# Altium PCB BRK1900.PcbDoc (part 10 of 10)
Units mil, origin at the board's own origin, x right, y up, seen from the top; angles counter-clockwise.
Board outline 8858.27 x 5905.51 mil, 10 copper layers (L1-TOP, L2-GND, L3-SIG1, L4-GND, L5-PWR, L6-PWR, L7-GND, L8-SIG2, L9-GND, L10-BOT), stack 48.824 mil thick; 507 components, 607 nets, 2498 pads, 2210 vias.
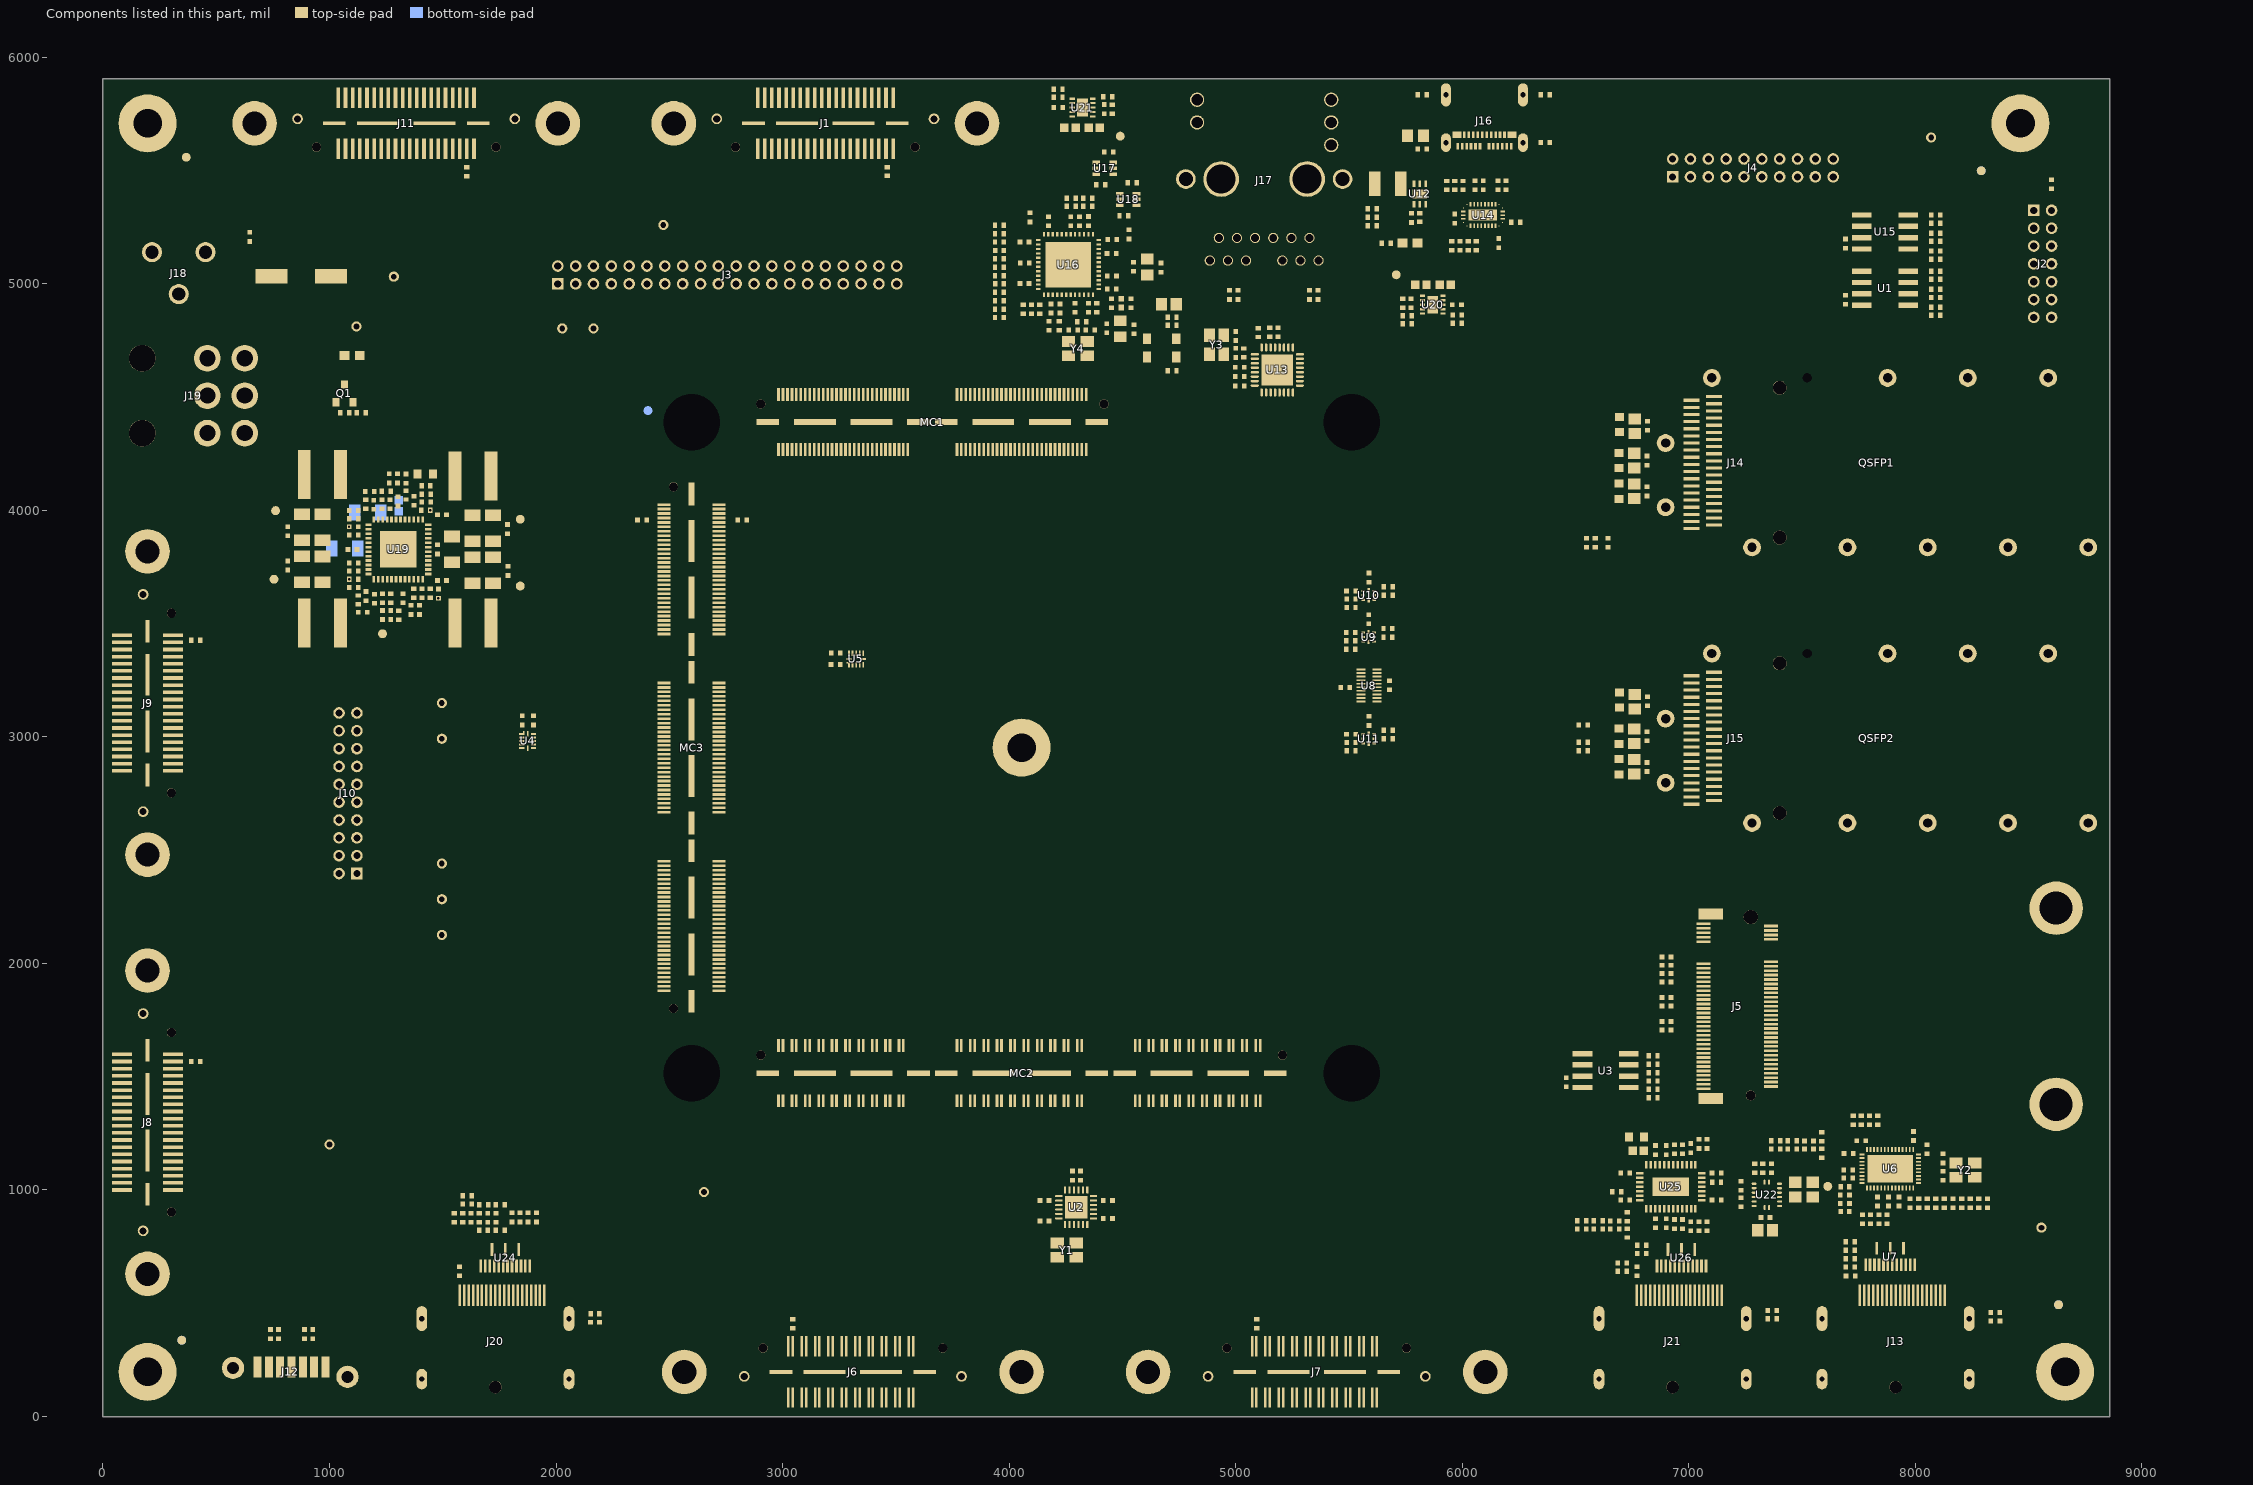
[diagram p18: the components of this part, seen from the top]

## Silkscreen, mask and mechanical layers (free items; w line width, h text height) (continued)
Drill Drawing:
  drawing of 183 lines, arcs and shapes, not listed
  text "DRILL TABLE" at 9113,5525.02 h50
  text "Symbol" at 9172.63,5408.47 h47.91
  text "Count" at 9519.93,5408.47 h47.91
  text "Finished Hole Size" at 9965.66,5408.47 h47.91
  text "Slot Length" at 10871.71,5408.47 h47.91
  text "Plated" at 11603.45,5408.47 h47.91
  text "Drill Layer Pair" at 11950.76,5408.47 h47.91
  text "Via/Pad" at 12753.04,5408.47 h47.91
  text "Hole Tolerance (+)" at 13156.22,5408.47 h47.91
  text "Hole Tolerance (-)" at 14054.29,5408.47 h47.91
  text "Comment" at 14952.35,5408.47 h47.91
  text "2214" at 9519.93,5308.66 h39.92
  text "10.00mil (0.254mm)" at 9965.66,5308.66 h39.92
  text "-" at 10871.71,5308.66 h39.92
  text "PTH" at 11603.45,5308.66 h39.92
  text "L1-TOP - L10-BOT" at 11950.76,5308.66 h39.92
  text "(Mixed)" at 12753.04,5308.66 h39.92
  text "3.00mil (0.076mm)" at 13156.22,5308.66 h39.92
  text "3.00mil (0.076mm)" at 14054.29,5308.66 h39.92
  text "2" at 9519.93,5208.86 h39.92
  text "23.62mil (0.600mm)" at 9965.66,5208.86 h39.92
  text "62.99mil (1.600mm)" at 10871.71,5208.86 h39.92
  text "PTH" at 11603.45,5208.86 h39.92
  text "L1-TOP - L10-BOT" at 11950.76,5208.86 h39.92
  text "Pad" at 12753.04,5208.86 h39.92
  text "3.00mil (0.076mm)" at 13156.22,5208.86 h39.92
  text "3.00mil (0.076mm)" at 14054.29,5208.86 h39.92
  text "6" at 9519.93,5109.05 h39.92
  text "23.62mil (0.600mm)" at 9965.66,5109.05 h39.92
  text "66.93mil (1.700mm)" at 10871.71,5109.05 h39.92
  text "PTH" at 11603.45,5109.05 h39.92
  text "L1-TOP - L10-BOT" at 11950.76,5109.05 h39.92
  text "Pad" at 12753.04,5109.05 h39.92
  text "3.00mil (0.076mm)" at 13156.22,5109.05 h39.92
  text "3.00mil (0.076mm)" at 14054.29,5109.05 h39.92
  text "E" at 9150.97,5099.06 h44.36
  text "2" at 9519.93,5009.24 h39.92
  text "23.62mil (0.600mm)" at 9965.66,5009.24 h39.92
  text "82.68mil (2.100mm)" at 10871.71,5009.24 h39.92
  text "PTH" at 11603.45,5009.24 h39.92
  text "L1-TOP - L10-BOT" at 11950.76,5009.24 h39.92
  text "Pad" at 12753.04,5009.24 h39.92
  text "3.00mil (0.076mm)" at 13156.22,5009.24 h39.92
  text "3.00mil (0.076mm)" at 14054.29,5009.24 h39.92
  text "6" at 9519.93,4909.43 h39.92
  text "23.62mil (0.600mm)" at 9965.66,4909.43 h39.92
  text "86.61mil (2.200mm)" at 10871.71,4909.43 h39.92
  text "PTH" at 11603.45,4909.43 h39.92
  text "L1-TOP - L10-BOT" at 11950.76,4909.43 h39.92
  text "Pad" at 12753.04,4909.43 h39.92
  text "3.00mil (0.076mm)" at 13156.22,4909.43 h39.92
  text "3.00mil (0.076mm)" at 14054.29,4909.43 h39.92
  text "14" at 9519.93,4809.63 h39.92
  text "25.00mil (0.635mm)" at 9965.66,4809.63 h39.92
  text "-" at 10871.71,4809.63 h39.92
  text "PTH" at 11603.45,4809.63 h39.92
  text "L1-TOP - L10-BOT" at 11950.76,4809.63 h39.92
  text "Pad" at 12753.04,4809.63 h39.92
  text "3.00mil (0.076mm)" at 13156.22,4809.63 h39.92
  text "3.00mil (0.076mm)" at 14054.29,4809.63 h39.92
  text "12" at 9519.93,4709.82 h39.92
  text "31.50mil (0.800mm)" at 9965.66,4709.82 h39.92
  text "-" at 10871.71,4709.82 h39.92
  text "PTH" at 11603.45,4709.82 h39.92
  text "L1-TOP - L10-BOT" at 11950.76,4709.82 h39.92
  text "Pad" at 12753.04,4709.82 h39.92
  text "3.00mil (0.076mm)" at 13156.22,4709.82 h39.92
  text "3.00mil (0.076mm)" at 14054.29,4709.82 h39.92
  text "94" at 9519.93,4610.01 h39.92
  text "31.50mil (0.800mm)" at 9965.66,4610.01 h39.92
  text "-" at 10871.71,4610.01 h39.92
  text "PTH" at 11603.45,4610.01 h39.92
  text "L1-TOP - L10-BOT" at 11950.76,4610.01 h39.92
  text "Pad" at 12753.04,4610.01 h39.92
  text "3.15mil (0.080mm)" at 13156.22,4610.01 h39.92
  text "3.15mil (0.080mm)" at 14054.29,4610.01 h39.92
  text "C" at 9150.97,4600.02 h44.36
  text "12" at 9519.93,4510.21 h39.92
  text "35.04mil (0.890mm)" at 9965.66,4510.21 h39.92
  text "-" at 10871.71,4510.21 h39.92
  text "PTH" at 11603.45,4510.21 h39.92
  text "L1-TOP - L10-BOT" at 11950.76,4510.21 h39.92
  text "Pad" at 12753.04,4510.21 h39.92
  text "5.00mil (0.127mm)" at 13156.22,4510.21 h39.92
  text "0.00mil (0.000mm)" at 14054.29,4510.21 h39.92
  text "A" at 9150.97,4500.21 h44.36
  text "18" at 9519.93,4410.4 h39.92
  text "40.16mil (1.020mm)" at 9965.66,4410.4 h39.92
  text "-" at 10871.71,4410.4 h39.92
  text "NPTH" at 11603.45,4410.4 h39.92
  text "L1-TOP - L10-BOT" at 11950.76,4410.4 h39.92
  text "Pad" at 12753.04,4410.4 h39.92
  text "3.00mil (0.076mm)" at 13156.22,4410.4 h39.92
  text "3.00mil (0.076mm)" at 14054.29,4410.4 h39.92
  text "2" at 9519.93,4310.59 h39.92
  text "41.34mil (1.050mm)" at 9965.66,4310.59 h39.92
  text "-" at 10871.71,4310.59 h39.92
  text "NPTH" at 11603.45,4310.59 h39.92
  text "L1-TOP - L10-BOT" at 11950.76,4310.59 h39.92
  text "Pad" at 12753.04,4310.59 h39.92
  text "3.00mil (0.076mm)" at 13156.22,4310.59 h39.92
  text "3.00mil (0.076mm)" at 14054.29,4310.59 h39.92
  text "J" at 9150.97,4300.6 h44.36
  text "22" at 9519.93,4210.78 h39.92
  text "41.34mil (1.050mm)" at 9965.66,4210.78 h39.92
  text "-" at 10871.71,4210.78 h39.92
  text "PTH" at 11603.45,4210.78 h39.92
  text "L1-TOP - L10-BOT" at 11950.76,4210.78 h39.92
  text "Pad" at 12753.04,4210.78 h39.92
  text "3.00mil (0.076mm)" at 13156.22,4210.78 h39.92
  text "3.00mil (0.076mm)" at 14054.29,4210.78 h39.92
  text "M" at 9150.97,4200.79 h44.36
  text "1" at 9519.93,4110.98 h39.92
  text "43.31mil (1.100mm)" at 9965.66,4110.98 h39.92
  text "-" at 10871.71,4110.98 h39.92
  text "NPTH" at 11603.45,4110.98 h39.92
  text "L1-TOP - L10-BOT" at 11950.76,4110.98 h39.92
  text "Pad" at 12753.04,4110.98 h39.92
  text "3.00mil (0.076mm)" at 13156.22,4110.98 h39.92
  text "3.00mil (0.076mm)" at 14054.29,4110.98 h39.92
  text "5" at 9519.93,4011.17 h39.92
  text "50.00mil (1.270mm)" at 9965.66,4011.17 h39.92
  text "-" at 10871.71,4011.17 h39.92
  text "PTH" at 11603.45,4011.17 h39.92
  text "L1-TOP - L10-BOT" at 11950.76,4011.17 h39.92
  text "Pad" at 12753.04,4011.17 h39.92
  text "4.00mil (0.102mm)" at 13156.22,4011.17 h39.92
  text "4.00mil (0.102mm)" at 14054.29,4011.17 h39.92
  text "N" at 9150.97,4001.18 h44.36
  text "2" at 9519.93,3911.36 h39.92
  text "53.15mil (1.350mm)" at 9965.66,3911.36 h39.92
  text "-" at 10871.71,3911.36 h39.92
  text "PTH" at 11603.45,3911.36 h39.92
  text "L1-TOP - L10-BOT" at 11950.76,3911.36 h39.92
  text "Pad" at 12753.04,3911.36 h39.92
  text "3.00mil (0.076mm)" at 13156.22,3911.36 h39.92
  text "3.00mil (0.076mm)" at 14054.29,3911.36 h39.92
  text "B" at 9150.97,3901.37 h44.36
  text "3" at 9519.93,3811.56 h39.92
  text "55.12mil (1.400mm)" at 9965.66,3811.56 h39.92
  text "-" at 10871.71,3811.56 h39.92
  text "NPTH" at 11603.45,3811.56 h39.92
  text "L1-TOP - L10-BOT" at 11950.76,3811.56 h39.92
  text "Pad" at 12753.04,3811.56 h39.92
  text "3.00mil (0.076mm)" at 13156.22,3811.56 h39.92
  text "3.00mil (0.076mm)" at 14054.29,3811.56 h39.92
  text "H" at 9150.97,3801.56 h44.36
  text "3" at 9519.93,3711.75 h39.92
  text "59.06mil (1.500mm)" at 9965.66,3711.75 h39.92
  text "-" at 10871.71,3711.75 h39.92
  text "PTH" at 11603.45,3711.75 h39.92
  text "L1-TOP - L10-BOT" at 11950.76,3711.75 h39.92
  text "Pad" at 12753.04,3711.75 h39.92
  text "3.00mil (0.076mm)" at 13156.22,3711.75 h39.92
  text "3.00mil (0.076mm)" at 14054.29,3711.75 h39.92
  text "4" at 9519.93,3611.94 h39.92
  text "61.02mil (1.550mm)" at 9965.66,3611.94 h39.92
  text "-" at 10871.71,3611.94 h39.92
  text "NPTH" at 11603.45,3611.94 h39.92
  text "L1-TOP - L10-BOT" at 11950.76,3611.94 h39.92
  text "Pad" at 12753.04,3611.94 h39.92
  text "3.00mil (0.076mm)" at 13156.22,3611.94 h39.92
  text "3.00mil (0.076mm)" at 14054.29,3611.94 h39.92
  text "D" at 9150.97,3601.95 h44.36
  text "2" at 9519.93,3512.13 h39.92
  text "62.00mil (1.575mm)" at 9965.66,3512.13 h39.92
  text "-" at 10871.71,3512.13 h39.92
  text "PTH" at 11603.45,3512.13 h39.92
  text "L1-TOP - L10-BOT" at 11950.76,3512.13 h39.92
  text "Pad" at 12753.04,3512.13 h39.92
  text "4.00mil (0.102mm)" at 13156.22,3512.13 h39.92
  text "4.00mil (0.102mm)" at 14054.29,3512.13 h39.92
  text "1" at 9519.93,3412.33 h39.92
  text "62.99mil (1.600mm)" at 9965.66,3412.33 h39.92
  text "-" at 10871.71,3412.33 h39.92
  text "NPTH" at 11603.45,3412.33 h39.92
  text "L1-TOP - L10-BOT" at 11950.76,3412.33 h39.92
  text "Pad" at 12753.04,3412.33 h39.92
  text "3.00mil (0.076mm)" at 13156.22,3412.33 h39.92
  text "3.00mil (0.076mm)" at 14054.29,3412.33 h39.92
  text "6" at 9519.93,3312.52 h39.92
  text "70.87mil (1.800mm)" at 9965.66,3312.52 h39.92
  text "-" at 10871.71,3312.52 h39.92
  text "PTH" at 11603.45,3312.52 h39.92
  text "L1-TOP - L10-BOT" at 11950.76,3312.52 h39.92
  text "Pad" at 12753.04,3312.52 h39.92
  text "3.00mil (0.076mm)" at 13156.22,3312.52 h39.92
  text "3.00mil (0.076mm)" at 14054.29,3312.52 h39.92
  text "12" at 9519.93,3212.71 h39.92
  text "106.30mil (2.700mm)" at 9965.66,3212.71 h39.92
  text "-" at 10871.71,3212.71 h39.92
  text "PTH" at 11603.45,3212.71 h39.92
  text "L1-TOP - L10-BOT" at 11950.76,3212.71 h39.92
  text "Pad" at 12753.04,3212.71 h39.92
  text "3.00mil (0.076mm)" at 13156.22,3212.71 h39.92
  text "3.00mil (0.076mm)" at 14054.29,3212.71 h39.92
  text "G" at 9150.97,3202.72 h44.36
  text "2" at 9519.93,3112.91 h39.92
  text "118.11mil (3.000mm)" at 9965.66,3112.91 h39.92
  text "-" at 10871.71,3112.91 h39.92
  text "NPTH" at 11603.45,3112.91 h39.92
  text "L1-TOP - L10-BOT" at 11950.76,3112.91 h39.92
  text "Pad" at 12753.04,3112.91 h39.92
  text "3.00mil (0.076mm)" at 13156.22,3112.91 h39.92
  text "3.00mil (0.076mm)" at 14054.29,3112.91 h39.92
  text "F" at 9150.97,3102.91 h44.36
  text "5" at 9519.93,3013.1 h39.92
  text "125.98mil (3.200mm)" at 9965.66,3013.1 h39.92
  text "-" at 10871.71,3013.1 h39.92
  text "PTH" at 11603.45,3013.1 h39.92
  text "L1-TOP - L10-BOT" at 11950.76,3013.1 h39.92
  text "Pad" at 12753.04,3013.1 h39.92
  text "3.00mil (0.076mm)" at 13156.22,3013.1 h39.92
  text "3.00mil (0.076mm)" at 14054.29,3013.1 h39.92
  text "O" at 9150.97,3003.11 h44.36
  text "2" at 9519.93,2913.29 h39.92
  text "128.00mil (3.251mm)" at 9965.66,2913.29 h39.92
  text "-" at 10871.71,2913.29 h39.92
  text "PTH" at 11603.45,2913.29 h39.92
  text "L1-TOP - L10-BOT" at 11950.76,2913.29 h39.92
  text "Pad" at 12753.04,2913.29 h39.92
  text "4.00mil (0.102mm)" at 13156.22,2913.29 h39.92
  text "4.00mil (0.102mm)" at 14054.29,2913.29 h39.92
  text "2" at 9519.93,2813.48 h39.92
  text "145.67mil (3.700mm)" at 9965.66,2813.48 h39.92
  text "-" at 10871.71,2813.48 h39.92
  text "PTH" at 11603.45,2813.48 h39.92
  text "L1-TOP - L10-BOT" at 11950.76,2813.48 h39.92
  text "Pad" at 12753.04,2813.48 h39.92
  text "3.00mil (0.076mm)" at 13156.22,2813.48 h39.92
  text "3.00mil (0.076mm)" at 14054.29,2813.48 h39.92
  text "4" at 9519.93,2713.68 h39.92
  text "250.00mil (6.350mm)" at 9965.66,2713.68 h39.92
  text "-" at 10871.71,2713.68 h39.92
  text "NPTH" at 11603.45,2713.68 h39.92
  text "L1-TOP - L10-BOT" at 11950.76,2713.68 h39.92
  text "Pad" at 12753.04,2713.68 h39.92
  text "3.00mil (0.076mm)" at 13156.22,2713.68 h39.92
  text "3.00mil (0.076mm)" at 14054.29,2713.68 h39.92
  text "I" at 9158.36,2703.68 h44.36
  text "2458 Total" at 9519.93,2613.87 h39.92
  text "Slot definitions :" at 9172.63,2510.72 h39.92
  text "Routed Path Length" at 9869.13,2510.72 h39.92
  text "= Calculated from tool start centre position to tool end centre position." at 10612.19,2510.72 h39.92
  text "Slot Length" at 9869.13,2437.5 h39.92
  text "= Routed Path Length + Tool Size = Slot length as defined in the PCB layout" at 10332.82,2437.5 h39.92
Doc-Assy-Top:
  lines w4.9: 6455.41,-1165.11 6455.41,-465.69 9394.83,-465.69 ; 6455.41,-929.08 9394.83,-929.08 ; 6899,-1165.11 6899,-929.08 ; 7587.2,-1165.11 7587.2,-929.08 ; 7724.8,-928.79 7724.8,-465.69 ; 8604.56,-1165.11 8604.56,-929.08
  lines w4.91: -809.63,527.32 -613.38,527.32 ; -809.63,2612.53 -613.38,2612.53 ; -809.63,4697.75 -613.38,4697.75 ; 1692.62,-1361.63 1692.62,-1165.38 ; 1692.62,6390.45 1692.62,6586.7 ; 4391.13,-1361.63 4391.13,-1165.38 ; 4391.13,6390.45 4391.13,6586.7 ; 5176.15,-1361.63 9591.89,-1361.63 ; 7089.64,-1361.63 7089.64,-1165.38 ; 7089.64,6390.45 7089.64,6586.7 ; 9395.64,527.32 9591.89,527.32 ; 9395.64,2612.53 9591.89,2612.53 ; 9395.64,4697.75 9591.89,4697.75 ; 9591.89,-1361.63 9591.89,6586.7 -809.63,6586.7 -809.63,-1361.63 9591.89,-1361.63 ; -613.38,-1165.38 -613.38,6390.45 9395.64,6390.45 9395.64,-1165.38 -613.38,-1165.38
  text "1" at 320.15,6457.32 h68.69
  text "2" at 3019.31,6457.32 h68.69
  text "3" at 5712.91,6457.32 h68.69
  text "4" at 8412.41,6457.32 h68.69
  text "NOTES: /  / 1. Hand place bottom-side components C113, C116, C140" at -411,5900.75 h50
  text "A" at -739.13,5651.55 h68.69
  text "A" at 9472.33,5651.55 h68.69
  text "B" at -739.13,3566.34 h68.69
  text "B" at 9472.33,3566.34 h68.69
  text "C" at -739.13,1481.12 h68.69
  text "C" at 9472.33,1481.12 h68.69
  text "TITLE:" at 6531.58,-542.92 h44.14
  text "Opal Kelly" at 7802.04,-573.82 h68.66
  text "D" at -739.13,-599.18 h68.69
  text "D" at 9472.33,-599.18 h68.69
  text "13500 SW 72nd Ave Suite 100" at 7802.04,-689.66 h68.66
  text "Portland, OR 97223" at 7802.04,-786.2 h68.66
  text "'.Part_Number' / Assembly Drawing" at 6563.33,-787.86 h68.66
  text "www.opalkelly.com" at 7802.04,-882.74 h68.66
  text "(Top)" at 6563.33,-899.67 h68.66
  text "REV:" at 6510.01,-994.48 h44.14
  text "SIZE:" at 6958.84,-994.48 h44.14
  text "ENGINEER:" at 7647.05,-994.48 h44.14
  text "DATE:" at 8664.4,-994.48 h44.14
  text "'.PCB_Revision'XX" at 6569.85,-1114.17 h68.66
  text "ANSI A" at 7018.68,-1114.17 h68.66
  text "NDK" at 7706.89,-1114.17 h68.66
  text ".PRINT_DATE" at 8724.24,-1114.17 h68.66
  text "1" at 320.15,-1300.94 h68.69
  text "2" at 3019.31,-1300.94 h68.69
  text "3" at 5712.91,-1300.94 h68.69
  text "4" at 8412.41,-1300.94 h68.69
Doc-Assy-Bot:
  lines w4.9: -611.4,-929.36 2327.29,-929.36 ; -611.4,-466.09 2327.29,-466.09 2327.29,-1165.33 ; 178.68,-1165.33 178.68,-929.36 ; 1058.21,-929.06 1058.21,-466.09 ; 1195.78,-1165.33 1195.78,-929.36 ; 1883.82,-1165.33 1883.82,-929.36
  lines w4.91: -808.42,526.69 -612.21,526.69 ; -808.42,2611.39 -612.21,2611.39 ; -808.42,4696.08 -612.21,4696.08 ; 1693.22,-1361.8 1693.22,-1165.6 ; 1693.22,6388.37 1693.22,6584.58 ; 3606.24,-1361.8 -808.42,-1361.8 ; 4391.07,-1361.8 4391.07,-1165.6 ; 4391.07,6388.37 4391.07,6584.58 ; 7088.91,-1361.8 7088.91,-1165.6 ; 7088.91,6388.37 7088.91,6584.58 ; 9394.34,526.69 9590.55,526.69 ; 9394.34,2611.39 9590.55,2611.39 ; 9394.34,4696.08 9590.55,4696.08 ; -808.42,-1361.8 9590.55,-1361.8 9590.55,6584.58 -808.42,6584.58 -808.42,-1361.8 ; -612.21,-1165.6 9394.34,-1165.6 9394.34,6388.37 -612.21,6388.37 -612.21,-1165.6
  text "4" at 370.77,6455.23 h68.67
  text "3" at 3069.61,6455.23 h68.67
  text "2" at 5762.55,6455.23 h68.67
  text "1" at 8461.05,6455.23 h68.67
  text "A" at -688.88,5649.65 h68.67
  text "A" at 9520.06,5649.65 h68.67
  text "B" at -688.88,3564.95 h68.67
  text "B" at 9520.06,3564.95 h68.67
  text "C" at -688.88,1480.25 h68.67
  text "C" at 9520.06,1480.25 h68.67
  text "TITLE:" at 2251.14,-543.3 h44.13
  text "Opal Kelly" at 981,-574.18 h68.64
  text "D" at -688.88,-599.54 h68.67
  text "D" at 9520.06,-599.54 h68.67
  text "13500 SW 72nd Ave Suite 100" at 981,-690 h68.64
  text "Portland, OR 97223" at 981,-786.52 h68.64
  text "'.Part_Number' / Assembly Drawing" at 2219.4,-788.17 h68.64
  text "www.opalkelly.com" at 981,-883.03 h68.64
  text "(Bottom)" at 2219.4,-899.96 h68.64
  text "DATE:" at 118.85,-994.74 h44.13
  text "ENGINEER:" at 1135.95,-994.74 h44.13
  text "SIZE:" at 1823.99,-994.74 h44.13
  text "REV:" at 2272.71,-994.74 h44.13
  text ".PRINT_DATE" at 59.02,-1114.4 h68.64
  text "NDK" at 1076.12,-1114.4 h68.64
  text "ANSI A" at 1764.16,-1114.4 h68.64
  text "'.PCB_Revision'XX" at 2212.88,-1114.4 h68.64
  text "4" at 370.77,-1301.13 h68.67
  text "3" at 3069.61,-1301.13 h68.67
  text "2" at 5762.55,-1301.13 h68.67
  text "1" at 8461.05,-1301.13 h68.67
Doc-Fab:
  lines w5: 10935.28,-537.72 10935.28,518.43 15474.46,518.43 ; 10935.28,328.43 12695.28,328.43 ; 10935.28,438.43 12695.28,438.43 ; 11355.28,-537.72 11355.28,518.43 ; 12695.28,-537.72 12695.28,518.43 ; 12695.28,-341.57 15475.28,-341.57 ; 12695.28,98.43 15474.46,98.43 ; 13255.28,-537.72 13255.28,-341.57 ; 13935.28,-341.57 13935.28,98.43 ; 14585.28,-537.72 14585.28,-341.57
  lines w5.49: -788.55,1850.61 -568.77,1850.61 ; -788.55,4460.55 -568.77,4460.55 ; -788.55,7070.49 -568.77,7070.49 ; 1958.75,-759.33 1958.75,-539.55 ; 1958.75,9460.64 1958.75,9680.43 ; 4706.06,-759.33 4706.06,-539.55 ; 4706.06,9460.64 4706.06,9680.43 ; 7453.36,-759.33 7453.36,-539.55 ; 7453.36,9460.64 7453.36,9680.43 ; 10200.67,-759.33 10200.67,-539.55 ; 10200.67,9460.64 10200.67,9680.43 ; 12947.97,-759.33 12947.97,-539.55 ; 12947.97,9460.64 12947.97,9680.43 ; 15475.49,1850.61 15695.28,1850.61 ; 15475.49,4460.55 15695.28,4460.55 ; 15475.49,7070.49 15695.28,7070.49 ; -788.55,-759.33 -788.55,9680.43 15695.28,9680.43 15695.28,-759.33 -788.55,-759.33 ; -568.77,-539.55 -568.77,9460.64 15475.49,9460.64 15475.49,-539.55 -568.77,-539.55
  text "1" at 564.59,9537.57 h76.92
  text "2" at 3307.13,9537.57 h76.92
  text "3" at 6042.72,9537.57 h76.92
  text "4" at 8797.35,9537.57 h76.92
  text "5" at 11543.55,9537.57 h76.92
  text "6" at 14296.35,9537.57 h76.92
  text "A" at -706.14,8281.5 h76.92
  text "A" at 15557.91,8281.5 h76.92
  text "B" at -706.14,5666.06 h76.92
  text "B" at 15557.91,5666.06 h76.92
  text "C" at -706.14,3056.12 h76.92
  text "C" at 15557.91,3056.12 h76.92
  text "REVISION:" at 10964.28,458.43 h40
  text "DESCRIPTION:" at 11394.28,458.43 h40
  text "D" at -706.14,451.68 h76.92
  text "D" at 15557.91,451.68 h76.92
  text "PART NUMBER:" at 12775.28,378.43 h75
  text "AXX" at 10965.28,358.43 h50
  text "Initial Release" at 11395.28,358.43 h50
  text "'.Part_Number'-PCB-'.PCB_Revision'XX" at 12795.28,98.43 h130
  text "TITLE:" at 12755.28,18.43 h40
  text "Opal Kelly" at 13995.28,-1.57 h60
  text "13500 SW 72nd Ave Suite 100" at 13995.28,-101.57 h60
  text "Portland, OR 97223" at 13995.28,-201.57 h60
  text "'.Part_Number' / Fabrication Drawing" at 12795.28,-281.57 h60
  text "www.opalkelly.com" at 13995.28,-301.57 h60
  text "SIZE:" at 12755.28,-401.57 h40
  text "ENGINEER:" at 13315.28,-401.57 h40
  text "DATE:" at 14635.28,-401.57 h40
  text "ANSI A" at 12795.28,-501.57 h60
  text "NDK" at 13355.28,-501.57 h60
  text ".PRINT_DATE" at 14675.28,-501.57 h60
  text "1" at 564.59,-682.41 h76.92
  text "2" at 3307.13,-682.41 h76.92
  text "3" at 6042.72,-682.41 h76.92
  text "4" at 8797.35,-682.41 h76.92
  text "5" at 11543.55,-682.41 h76.92
  text "6" at 14296.35,-682.41 h76.92

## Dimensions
0,0 to 8858.27,0 on Dimensions
0,0 to 0,5905.51 on Dimensions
